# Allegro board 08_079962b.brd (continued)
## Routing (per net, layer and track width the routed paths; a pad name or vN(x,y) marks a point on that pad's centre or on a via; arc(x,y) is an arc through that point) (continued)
VIN: length 127.4
  TOP w0.254: v2(93.28,105.81) v2(92.94,105.81) v2(92.58,105.81) v2(92.23,105.81) ; R51.1 v1(89.15,83.69) ; v2(93.22,40.5) v2(92.91,40.5) v2(92.58,40.5) ; U2.11 96.16,89.67 C49.1 ; v2(92.58,106.81) v2(92.94,106.81) ; R10.1 v1(89.15,16.38) ; v2(93.22,39.5) v2(92.91,39.5) v2(92.58,39.5) v2(92.23,39.5) ; C16.1 96.16,22.36 U1.11 ; v2(92.58,107.81) v2(92.94,107.81) v2(93.28,107.81)
  TOP w0.381: JP2.3 v1(13.97,17.78)
  L2_GND w0.254: v2(91.88,107.81) v2(92.23,107.81) v2(92.58,107.81) v2(92.94,107.81) v2(93.28,107.81) ; v2(91.88,39.5) v2(92.23,39.5) v2(92.58,39.5) v2(92.91,39.5) v2(93.22,39.5) ; v2(93.22,40.5) v2(92.91,40.5) v2(92.58,40.5) v2(92.23,40.5) v2(91.88,40.5) ; v2(93.28,106.81) v2(92.94,106.81) v2(92.58,106.81) v2(92.23,106.81) v2(91.88,106.81) ; v2(91.88,38.5) v2(92.23,38.5) v2(92.58,38.5) v2(92.91,38.5) v2(93.22,38.5) ; v2(93.28,105.81) v2(92.94,105.81) v2(92.58,105.81) v2(92.23,105.81) v2(91.88,105.81)
  L4_SIG w0.381: v2(96.65,89.66) 94.74,89.66 91.69,86.61 91.69,85.72 89.66,83.69 v1(89.15,83.69) 84.46,83.69 v1(69.22,98.93) ; v1(69.22,31.62) 84.46,16.38 v1(89.15,16.38) 89.41,16.38 91.57,18.54 91.57,19.18 94.74,22.35 v2(96.71,22.35) ; v1(25.27,34.8) 13.97,23.5 v1(13.97,17.78)
  L4_SIG w0.508: v2(97.09,22.35) v2(96.71,22.35) ; v2(97.03,89.66) v2(96.65,89.66)
  L5_GND w0.254: v2(93.28,106.81) v2(92.94,106.81) v2(92.58,106.81) v2(92.23,106.81) v2(91.88,106.81) ; v2(91.88,107.81) v2(92.23,107.81) v2(92.58,107.81) v2(92.94,107.81) v2(93.28,107.81) ; v2(91.88,105.81) v2(92.23,105.81) v2(92.58,105.81) v2(92.94,105.81) v2(93.28,105.81) ; v2(93.22,40.5) v2(92.91,40.5) v2(92.58,40.5) v2(92.23,40.5) v2(91.88,40.5) ; v2(93.22,39.5) v2(92.91,39.5) v2(92.58,39.5) v2(92.23,39.5) v2(91.88,39.5) ; v2(93.22,38.5) v2(92.91,38.5) v2(92.58,38.5) v2(92.23,38.5) v2(91.88,38.5)
  vias: v1(43.81,111.25) v1(43.81,109.35) v1(43.81,107.44) v1(43.81,102.74) v1(43.81,100.84) v1(43.81,98.93) v1(43.81,43.94) v1(43.81,42.04) v1(43.81,40.13) v1(43.81,35.43) v1(43.81,33.53) v1(43.81,31.62) v1(46.35,111.25) v1(46.35,109.35) v1(46.35,107.44) v1(46.35,102.74) v1(46.35,100.84) v1(46.35,98.93) v1(46.35,43.94) v1(46.35,42.04) v1(46.35,40.13) v1(46.35,35.43) v1(46.35,33.53) v1(46.35,31.62) v1(55.24,111.25) v1(55.24,109.35) v1(55.24,107.44) v1(55.24,102.74) v1(55.24,100.84) v1(55.24,98.93) v1(55.24,43.94) v1(55.24,42.04) v1(55.24,40.13) v1(55.24,35.43) v1(55.24,33.53) v1(55.24,31.62) v1(57.79,111.25) v1(57.79,109.35) v1(57.79,107.44) v1(57.79,102.74) v1(57.79,100.84) v1(57.79,98.93) v1(57.79,43.94) v1(57.79,42.04) v1(57.79,40.13) v1(57.79,35.43) v1(57.79,33.53) v1(57.79,31.62) v1(66.67,111.25) v1(66.67,109.35) v1(66.67,107.44) v1(66.67,102.74) v1(66.67,100.84) v1(66.67,98.93) v1(66.67,43.94) v1(66.67,42.04) v1(66.67,40.13) v1(66.67,35.43) v1(66.67,33.53) v1(66.67,31.62) v1(69.22,111.25) v1(69.22,109.35) v1(69.22,107.44) v1(69.22,102.74) v1(69.22,100.84) v1(69.22,43.94) v1(69.22,42.04) v1(69.22,40.13) v1(69.22,35.43) v1(69.22,33.53) v1(89.15,39.5) v1(89.41,106.81) v1(90.04,110.11) v1(90.04,103.5) v1(90.17,108.71) v1(90.17,104.9) v1(90.17,42.8) v1(90.17,41.4) v1(90.17,37.59) v1(90.17,36.2)
CLKOUT1: length 81.5
  TOP w0.254: U1.30 v2(106.67,23.36)
  L3_SIG w0.254: JP1.2 136.94,82.64 136.27,83.31 129.41,83.31 128.02,81.91 128.02,79.63 107.82,59.44 107.82,46.74 104.39,43.31 104.39,26.16 105.66,24.89 105.66,24.37 v2(106.67,23.36)
EN1: length 130.4
  TOP w0.254: Q1.1 23.19,13.16 v1(23.11,13.08)
  TOP w0.381: R88.1 v1(23.11,126.87)
  L4_SIG w0.254: v1(23.11,126.87) 23.11,121.54 27.69,116.97 27.69,27.69 23.11,23.11 v1(23.11,13.08) 16.32,6.28 16.32,6.16 TP36.1
EN/UVLO_1: length 72.8
  TOP w0.254: R10.2 91.36,16.84 v2(91.31,16.89) ; Q2.3 v1(31.24,14.73)
  L4_SIG w0.254: TP7.1 30.48,13.97 v1(31.24,14.73) 31.62,15.11 90.55,15.11 91.31,15.88 v2(91.31,16.89)
EN/UVLO_2: length 100.3
  TOP w0.254: R51.2 v2(91.36,83.36) ; Q4.3 v1(28.7,130.68)
  L4_SIG w0.254: v2(91.36,83.36) 91.36,82.55 91.11,82.3 82.17,82.3 68.33,96.14 66.67,96.14 57.4,105.41 43.31,105.41 37.85,110.87 37.85,117.73 28.7,126.87 v1(28.7,130.68) 27.94,131.44 TP28.1
ICTRL_2: length 179.6
  TOP w0.254: R1.2 v1(105.41,14.1) ; R43.2 R44.1 107.7,85.22 106.74,86.17 U2.21
  L3_SIG w0.254: v2(107.12,83.76) 105.54,82.17 105.54,46.35 103.12,43.94 103.12,25.78 104.46,24.45 104.46,19.24 105.41,18.29 v1(105.41,14.1)
  L4_SIG w0.254: v2(107.12,83.76) 107.31,83.95 110.43,83.95 111.82,82.55 113.35,82.55 116.33,79.57 124.27,79.57 131.25,86.55 143.19,86.55 151.32,94.68 151.32,123.38 163.19,135.25 TP30.1
IGND: length 118.8
  TOP w0.254: R23.1 v2(96.27,15.18) 96.79,15.18 97.92,16.31 97.92,17.2 99.08,18.36 U1.19 ; U2.19 99.08,85.67 97.92,84.51 97.92,83.62 96.79,82.49 v2(96.27,82.49) R64.1
  L3_SIG w0.381: v2(96.27,82.49) 96.52,82.23 96.52,80.9 81.15,65.53 81.15,21.27 78.74,18.86 TP15.1
  L4_SIG w0.381: TP15.1 82.42,8.76 87.67,8.76 92.63,13.72 93.77,13.72 95.23,15.18 v2(96.27,15.18)
INJ1.1: length 83.4
  TOP w0.254: v2(112.65,16.38) R40.2 113.47,16.38 114.62,17.53 R39.1 ; TP20.1 v2(123.76,19.69)
  TOP w0.381: v2(129.67,82.11) 129.21,82.56 R93.1
  L3_SIG w0.254: v2(129.67,82.11) 129.67,77.34 121.67,69.34 121.67,21.78 v2(123.76,19.69)
  L4_SIG w0.254: v2(123.76,19.69) 121.6,17.53 113.79,17.53 v2(112.65,16.38)
INTVCC1: length 65.9
  TOP w0.254: v2(112.08,25.15) R2.1 ; R13.2 114.86,21.89 v1(114.87,21.91) 114.86,21.92 R14.2 ; C4.1 96.27,19.38 98.25,21.36 U1.13 ; v2(112.14,20.96) R6.1 ; R3.1 v2(106.55,14.1) ; D15.C v2(96.71,17.7)
  TOP w0.381: v2(95.88,14.22) TP8.1
  L3_SIG w0.254: v2(112.14,20.96) 113.92,20.96 v1(114.87,21.91) ; v2(112.14,20.96) 112.14,22.1 112.65,22.61 112.65,23.75 112.08,24.32 v2(112.08,25.15) 113.28,25.15 114.94,26.8 v2(114.94,29.08) ; v2(112.14,20.96) 111.38,20.96 109.85,19.43 109.85,17.91 106.55,14.61 v2(106.55,14.1) 106.55,13.59 105.79,12.83 97.28,12.83 v2(95.88,14.22) 95.63,14.48 95.63,16.62 v2(96.71,17.7) 96.71,21.02 90.68,27.05 v2(90.68,29.59)
  BOTTOM w0.381: D2.A 114.05,29.97 v2(114.94,29.08) ; v2(90.68,29.59) 91.06,29.97 D1.A
INTVCC2: length 67.1
  TOP w0.254: v2(112.08,92.39) 111.62,92.39 R45.1 ; R43.1 v2(106.55,81.6) ; R54.2 114.86,89.2 v1(114.87,89.22) 114.86,89.23 R55.2 ; U2.13 98.25,88.67 96.27,86.69 C37.1 ; D16.C v2(96.71,85.01) ; v2(112.14,88.26) R47.1
  TOP w0.381: TP29.1 v2(95.88,81.27)
  L3_SIG w0.254: v2(95.88,81.27) 95.5,81.65 95.5,83.81 v2(96.71,85.01) ; v2(96.71,85.01) 97.33,85.01 97.79,85.47 109.22,85.47 109.35,85.34 ; v2(96.71,85.01) 96.71,87.25 90.68,93.28 v2(90.68,97.03) ; 109.35,85.34 109.35,83.31 108.59,82.55 107.51,82.55 v2(106.55,81.6) ; 109.35,85.34 109.35,85.98 111.63,88.26 v2(112.14,88.26) 113.92,88.26 v1(114.87,89.22) 113.66,90.42 113.66,92.46 ; 113.66,92.46 113.6,92.39 v2(112.08,92.39) ; 113.66,92.46 113.66,92.96 114.94,94.23 v2(114.94,97.28)
  BOTTOM w0.381: v2(90.68,97.03) 90.93,97.28 D7.A ; v2(114.94,97.28) D8.A
ISHARE: length 117.3
  TOP w0.254: U2.20 105.77,85.28 105.41,84.92 v2(105.41,84.33) C39.1 ; C6.1 v2(104.27,17.02) 104.27,17.53 105.1,18.36 U1.20
  L3_SIG w0.381: TP11.1 91.44,9.59 86.87,14.16 86.87,17.53 82.42,21.97 82.42,64.77 101.98,84.33 v2(105.41,84.33)
  L4_SIG w0.381: TP11.1 103.38,17.02 v2(104.27,17.02)
OUT: length 131.2
  TOP w0.254: TP19.1 v2(123.76,15.88) ; 141.42,39.75 140.33,39.75 140.08,39.5 140.08,31.93 R37.1 ; 141.42,39.75 R36.2 ; 141.42,39.75 R35.2 ; R78.1 140.08,99.24 140.08,106.81 140.33,107.06 141.42,107.06 ; R40.1 v2(115.44,16.38)
  TOP w0.381: TP40.1 v2(124.4,81.28) ; R81.1 v2(115.38,83.69) ; R76.2 R77.2
  L4_SIG w0.381: v1(149.86,34.8) 148.59,33.53 148.59,26.29 138.18,15.88 v2(123.76,15.88) 115.95,15.88 v2(115.44,16.38) ; v2(115.38,83.69) 116.21,83.69 118.62,81.28 v2(124.4,81.28) 131.32,88.2 142.18,88.2 148.65,94.68 148.65,100.77 v1(147.32,102.11)
  vias: v1(144.14,114.3) v1(144.14,113.03) v1(144.14,111.76) v1(144.14,110.49) v1(144.14,109.22) v1(144.14,107.95) v1(144.14,106.68) v1(144.14,105.41) v1(144.14,104.14) v1(144.14,102.87) v1(144.14,101.6) v1(144.14,100.33) v1(144.14,46.99) v1(144.14,45.72) v1(144.14,44.45) v1(144.14,43.18) v1(144.14,41.91) v1(144.14,40.64) v1(144.14,39.37) v1(144.14,38.1) v1(144.14,36.83) v1(144.14,35.56) v1(144.14,34.29) v1(144.14,33.02) v1(147.32,113.16) v1(147.32,111.63) v1(147.32,109.98) v1(147.32,105.28) v1(147.32,103.76) v1(147.32,45.85) v1(147.32,44.32) v1(147.32,42.67) v1(147.32,37.97) v1(147.32,36.45) v1(147.32,34.8) v1(149.86,113.16) v1(149.86,111.63) v1(149.86,109.98) v1(149.86,105.28) v1(149.86,103.76) v1(149.86,102.11) v1(149.86,45.85) v1(149.86,44.32) v1(149.86,42.67) v1(149.86,37.97) v1(149.86,36.45)
PGOOD1: length 67.7
  TOP w0.254: U1.25 v2(109.35,20.86) 109.84,20.86 R6.2
  L4_SIG w0.254: v2(109.35,20.86) 108.84,20.35 108.84,17.91 111.51,15.24 112.52,15.24 117.35,10.41 158.5,10.41 TP10.1
PGOOD2: length 88.9
  TOP w0.254: U2.25 v2(109.35,88.17) 109.84,88.17 R47.2
  L4_SIG w0.254: v2(109.35,88.17) 110.52,88.17 111,87.69 114.24,87.69 114.81,88.26 119.63,88.26 120.9,89.53 138.68,89.53 145.35,96.2 145.35,130.11 150.5,135.25 TP31.1
UNNAMED_1_ADLT8292_I154_BG1N: length 3.4
  TOP w0.254: U1.2 98.79,26.86
  TOP w0.381: 98.79,26.86 98.55,27.1 R18.1
UNNAMED_1_ADLT8292_I154_BG1P: length 1.8
  TOP w0.254: 99.97,27.79 99.94,27.82 ; U1.1 99.97,27.5
  TOP w0.381: R17.1 99.69,28.07 99.94,27.82 ; 99.97,27.5 99.97,27.79
UNNAMED_1_ADLT8292_I154_BG2N: length 3.5
  TOP w0.254: 107,27.11 106.74,26.86 U1.37
  TOP w0.381: R30.1 107.19,27.3 107,27.11
UNNAMED_1_ADLT8292_I154_BG2P: length 1.9
  TOP w0.254: U1.38 105.77,27.5
  TOP w0.381: R29.1 106.04,28.07 105.77,27.79 105.77,27.5
UNNAMED_1_ADLT8292_I154_BST1: length 4.7
  TOP w0.254: U1.4 98.85,25.86 97.66,27.05 97.66,27.89 C22.1
UNNAMED_1_ADLT8292_I154_BST2: length 4.5
  TOP w0.254: C28.1 108.19,28.13 108.19,27.42 106.63,25.86 U1.35
UNNAMED_1_ADLT8292_I154_EN: length 9.3
  TOP w0.254: U1.12 97.55,21.86 96.27,20.57 91.74,20.57 C9.2
UNNAMED_1_ADLT8292_I154_ICTRL: length 55.8
  TOP w0.254: U1.21 106.74,18.86 107.7,17.91 R4.1 107.14,16.43 v2(107.12,16.45) 107.11,16.43 R3.2 R1.1
  L4_SIG w0.254: TP9.1 147.83,7.75 113.03,7.75 108.71,12.07 108.71,14.86 v2(107.12,16.45)
UNNAMED_1_ADLT8292_I154_ISN: length 52.4
  TOP w0.254: v2(98.55,19.05) 98.86,19.36 U1.17 ; R38.1 v2(138.43,27.05)
  TOP w0.381: R38.1 R38.2
  TOP w0.762: TP18.1 138.43,26.47 R38.1 ; TP17.1 141.6,26.09 R38.2
  L4_SIG w0.254: v2(138.43,27.05) 137.92,27.56 132.08,27.56 129.67,25.15 115.44,25.15 112.27,21.97 108.71,21.97 105.66,18.92 98.68,18.92 v2(98.55,19.05)
UNNAMED_1_ADLT8292_I154_LSN: length 7.4
  TOP w0.254: 94.02,23.36 C18.2 92.81,23.32 R20.1 ; 94.02,23.36 94.03,23.37 ; 94.02,23.36 U1.9
UNNAMED_1_ADLT8292_I154_LSP: length 7.9
  TOP w0.254: U1.8 96.54,23.86 95.45,24.94 C18.1 92.81,24.94 R19.1
UNNAMED_1_ADLT8292_I154_RDT1: length 7.7
  TOP w0.254: U1.26 108.86,21.36 109.19,21.69 112.24,21.69 112.6,21.34 R13.1
UNNAMED_1_ADLT8292_I154_RDT2: length 7.7
  TOP w0.254: U1.27 108.47,21.86 108.76,22.15 112.27,22.15 112.6,22.48 R14.1
UNNAMED_1_ADLT8292_I154_RT: length 4.4
  TOP w0.254: U1.28 108.21,22.36 108.76,22.91 R8.1
UNNAMED_1_ADLT8292_I154_SS: length 4.4
  TOP w0.254: C10.1 109.3,19.81 108.75,20.36 U1.24
UNNAMED_1_ADLT8292_I154_SW1: length 79.5
  TOP w0.254: v1(94.87,39.75) 95.12,39.5 M2.5 ; v1(94.87,38.48) 94.89,38.5 M2.3 ; v1(98.68,47.88) 98.68,46.86 ; v1(94.36,38.48) 94.36,38.62 93.98,39 M1.4 ; M1.6 94.11,40 v1(94.36,39.75) ; v1(93.22,37.72) 93.1,37.84 M1.2 ; v1(94.87,41.02) 94.87,41 95.38,40.5 M2.7 ; M1.8 94.34,41 v1(94.36,41.02) ; R19.2 v1(90.42,24.77) ; v1(96.9,24.64) 97.18,24.36 U1.7
  TOP w0.508: C22.2 v1(96.9,30.99) ; R26.1 95.19,46.86 102.16,46.86 R27.1
  L3_SIG w0.254: v1(98.68,47.88) 98.55,48.01 89.66,48.01 84.33,42.67 84.33,29.21 89.15,24.38 90.04,24.38 v1(90.42,24.77)
  L3_SIG w0.508: v1(94.36,38.48) 94.36,33.53 v1(96.9,30.99) v1(96.9,24.64)
  BOTTOM w0.254: 93.17,36.25 93.22,36.3 v1(93.22,37.72)
  vias: v1(94.36,42.29) v1(94.87,42.29) v1(95.25,45.97) v1(95.25,45.47) v1(95.25,44.96) v1(95.76,45.97) v1(95.76,45.47) v1(95.76,44.96) v1(96.27,45.97) v1(96.27,45.47) v1(96.27,44.96) v1(96.77,45.97) v1(96.77,45.47) v1(96.77,44.96)
UNNAMED_1_ADLT8292_I154_SW2: length 35.4
  TOP w0.254: v1(111.86,40.53) 112.33,41 M4.8 ; M3.3 110.9,38.5 v1(111.4,39.01) ; v1(111.4,41.04) 110.86,40.5 M3.7 ; U1.32 107.21,24.36 107.31,24.26 v1(107.95,24.26) ; v1(111.86,39.51) 112.35,40 M4.6 ; M3.5 110.88,39.5 v1(111.4,40.02) ; M4.4 112.36,39 v1(111.86,38.5)
  TOP w0.508: C28.2 108.84,30.4 v1(108.84,30.99) 108.84,31.71 D5.A
  L3_SIG w0.508: v1(107.95,24.26) 108.84,25.15 v1(108.84,30.99) 108.84,32.51 111,34.67 111,38.6 v1(111.4,39.01)
  BOTTOM w0.254: v2(114,37.95) v2(114.36,37.95) 114.58,37.95 114.84,37.69 114.84,36.25 114.58,35.99 J8.5
  vias: v1(110.62,52.7) v1(110.62,52.2) v1(110.87,47.37) v1(110.87,46.86) v1(110.87,46.35) v1(111.12,52.7) v1(111.12,52.2) v1(111.38,47.36) v1(111.38,46.86) v1(111.38,46.35) v1(111.4,42.8) v1(111.63,52.7) v1(111.63,52.2) v1(111.89,47.37) v1(111.89,46.86) v1(111.89,46.35) v1(111.86,42.29) v1(112.14,52.7) v1(112.14,52.19) v1(112.4,47.37) v1(112.4,46.86) v1(112.4,46.35) v1(112.65,52.7) v1(112.65,52.2) v1(113.16,52.7) v1(113.16,52.2) v2(111.58,37.85) v2(111.58,37.49) v2(111.94,37.85) v2(111.94,37.49) v2(112.3,37.85) v2(112.3,37.49) v2(114,37.59) v2(114,37.23) v2(114,36.88) v2(114.36,37.59) v2(114.36,37.23) v2(114.36,36.88)
UNNAMED_1_ADLT8292_I154_SYNC: length 81.4
  TOP w0.254: U1.29 107.82,22.86 108.71,23.75 109.68,23.75 R7.1 109.93,24.56 v2(109.92,24.57) 109.93,24.59 R2.2
  L2_GND w0.254: v2(109.92,24.57) 124.27,24.57 125.98,22.86 TP12.1
UNNAMED_1_ADLT8292_I154_TG1N: length 4.8
  TOP w0.254: U1.6 97.82,24.86 97.67,25.02
  TOP w0.381: R16.1 96.52,26.16 97.67,25.02
UNNAMED_1_ADLT8292_I154_TG1P: length 5.1
  TOP w0.254: 98.17,25.65 98.46,25.36 U1.5
  TOP w0.305: R15.1 96.52,27.3 98.17,25.65
UNNAMED_1_ADLT8292_I154_TG2N: length 4.8
  TOP w0.254: U1.33 107.54,24.86 107.7,25.02
  TOP w0.381: 107.7,25.02 108.97,26.29 R32.1
UNNAMED_1_ADLT8292_I154_TG2P: length 5
  TOP w0.254: 107.19,25.53 107.02,25.36 U1.34
  TOP w0.381: 107.19,25.53 109.09,27.43 R31.1
UNNAMED_1_ADLT8292_I154_VC: length 15.9
  TOP w0.254: U1.22 107.02,19.36 108.71,17.66 108.71,15.75 109.22,15.24 R9.1 109.93,14.68 v2(109.92,14.67) 109.93,14.66 C12.1 ; TP13.1 114.05,9.27
  L4_SIG w0.254: v2(113.98,9.27) 109.92,13.34 v2(109.92,14.67)
UNNAMED_1_ADLT8292_I154_VOUT: length 67.5
  TOP w0.254: C19.1 v1(96.39,16.32) 96.79,16.32 97.43,16.97 97.43,19.34 98.45,20.36 U1.15 ; R34.1 139.57,31.93 139.57,39.5 139.32,39.75 138.18,39.75 ; R35.1 138.23,39.81 138.18,39.75 ; R36.1 138.23,39.7 138.18,39.75
  L2_GND w0.254: v2(114.35,39.5) v2(114,39.5) v2(113.66,39.5) v2(113.32,39.5) v2(112.97,39.5) ; v2(114.35,38.5) v2(114,38.5) v2(113.66,38.5) v2(113.32,38.5) v2(112.97,38.5) ; v2(112.97,40.5) v2(113.32,40.5) v2(113.66,40.5) v2(114,40.5) v2(114.35,40.5)
  L4_SIG w0.254: v1(116.08,36.32) 116.08,28.07 112.4,24.38 111.12,24.38 110.24,23.5 107.95,23.5 105.03,20.57 97.92,20.57 97.35,20 97.35,16.83 96.84,16.32 v1(96.39,16.32)
  L5_GND w0.254: v2(114.35,38.5) v2(114,38.5) v2(113.66,38.5) v2(113.32,38.5) v2(112.97,38.5) ; v2(114.35,40.5) v2(114,40.5) v2(113.66,40.5) v2(113.32,40.5) v2(112.97,40.5) ; v2(114.35,39.5) v2(114,39.5) v2(113.66,39.5) v2(113.32,39.5) v2(112.97,39.5)
  vias: v1(115.44,43.62) v1(115.44,42.04) v1(116.08,42.8) v1(116.08,41.4) v1(116.08,37.59) v1(116.84,39.5) v1(124.46,54.7) v1(124.46,53.18) v1(124.46,51.66) v1(128.27,54.7) v1(128.27,53.18) v1(128.27,51.66) v1(132.08,54.7) v1(132.08,53.18) v1(132.08,51.66) v1(135.89,54.7) v1(135.89,53.18) v1(135.89,51.66) v1(135.89,46.99) v1(135.89,45.72) v1(135.89,44.45) v1(135.89,43.18) v1(135.89,41.91) v1(135.89,40.64) v1(135.89,39.37) v1(135.89,38.1) v1(135.89,36.83) v1(135.89,35.56) v1(135.89,34.29) v1(135.89,33.02)
UNNAMED_1_CAP_I52_N2: length 7.4
  TOP w0.254: C31.2 109.6,17.53 107.27,19.86 U1.23 ; C31.2 R41.2 ; C31.2 R42.1
UNNAMED_1_CAP_I61_N1: length 48.3
  TOP w0.254: U1.16 98.6,19.86 v2(98.3,19.56)
  TOP w0.762: TP16.1 136.91,28.45 v2(138.43,28.45) C30.1
  L4_SIG w0.254: v2(138.43,28.45) 138.05,28.07 131.83,28.07 129.41,25.65 115.19,25.65 112.01,22.48 108.46,22.48 105.54,19.56 v2(98.3,19.56)
UNNAMED_1_CNBNC5P_I74_CNTR: length 26.6
  TOP w0.254: R31.2 v1(112.14,27.43) 112.64,27.94 112.64,37.08 v1(113.15,37.59) 113.15,27.3 v1(112.14,26.29) R32.2
  BOTTOM w0.254: J8.1 113.15,35.17 v1(113.15,37.59)
UNNAMED_1_CNBNC5P_I82_CNTR: length 19.3
  TOP w0.254: R30.2 v1(107.19,31.37) 107.19,32.41 109.09,34.31 v1(109.09,37.59) 108.58,37.08 108.58,34.51 106.04,31.98 v1(106.04,31.37) R29.2
  L3_SIG w0.254: v2(106.68,36.2) 107.69,36.2 v1(109.09,37.59)
  BOTTOM w0.381: J7.1 v2(106.68,36.2)
UNNAMED_1_CNBNC5P_I107_CNTR: length 29.6
  TOP w0.254: v1(93.47,26.16) R16.2 ; 92.18,37.72 92.59,37.31 92.59,27.81 93.1,27.3 93.48,27.3 ; v1(93.47,27.3) R15.2 ; M1.1 92.07,37.72 v1(92.07,37.72) 92.07,27.18 93.1,26.16 93.48,26.16
  BOTTOM w0.254: v1(92.07,37.72) 92.07,35.69 92.84,34.92 J5.1
UNNAMED_1_CNBNC5P_I114_CNTR: length 21.7
  TOP w0.254: 96.29,37.72 96.65,37.36 96.65,34.7 99.7,31.64 99.7,31.24 ; 98.56,31.24 98.56,32.08 96.14,34.49 v1(96.14,37.72) 96.13,37.72 M2.1 ; R18.2 v1(98.55,31.24) ; R17.2 v1(99.69,31.24)
  L3_SIG w0.254: v1(96.14,37.72) 98.3,35.56 v2(99.44,35.56)
  BOTTOM w0.381: J6.1 v2(99.44,35.56)
UNNAMED_1_CNTP1P_I232_N1: length 10
  TOP w0.381: JP2.1 9.95,13.55 TP43.1
UNNAMED_1_DIOSCHOTTKY_I102_N: length 1.7
  TOP w0.508: R22.1 v1(111,30.86)
  BOTTOM w0.381: D2.C 111,30.48 v1(111,30.86)
UNNAMED_1_DIOSCHOTTKY_I103_N: length 1.7
  TOP w0.508: R21.1 v1(94.62,30.86)
  BOTTOM w0.381: v1(94.62,30.86) 94.62,30.48 D1.C
UNNAMED_1_IND_I264_N1: length 49.2
  TOP w0.254: v1(98.68,48.64) 98.68,49.66 ; R20.2 v1(90.42,23.5)
  TOP w0.508: R27.2 102.16,49.66 95.19,49.66 R26.2
  L3_SIG w0.254: v1(90.42,23.5) 90.04,23.88 88.9,23.88 83.82,28.96 83.82,42.93 89.41,48.51 98.55,48.51 v1(98.68,48.64)
  vias: v1(94.62,51.18) v1(94.62,50.67) v1(95.12,51.18) v1(95.12,50.67) v1(95.63,51.18) v1(95.63,50.67) v1(100.33,52.7) v1(100.33,52.2) v1(100.84,52.7) v1(100.84,52.2) v1(101.35,52.7) v1(101.35,52.2) v1(101.6,51.18) v1(101.6,50.67) v1(101.85,52.7) v1(101.85,52.2) v1(102.11,51.18) v1(102.11,50.67) v1(102.36,52.7) v1(102.36,52.2) v1(102.62,51.18) v1(102.62,50.67) v1(102.87,52.7) v1(102.87,52.2)
UNNAMED_1_RES_I248_N1: length 15.9
  TOP w0.381: Q3.1 20.65,129.11 v1(20.57,129.03) 20.78,128.83 R89.1 R88.2
  L4_SIG w0.254: v1(20.57,129.03) 20.57,130.56 15.24,135.89 TP44.1
UNNAMED_1_RES_I252_N1: length 130.7
  TOP w0.381: R86.1 19.3,129.49 v1(19.3,129.16) ; JP2.2 v1(14.86,15.24) 18.8,15.24 20.12,13.92 R84.1
  L4_SIG w0.381: v1(19.3,129.16) 19.3,122.81 26.54,115.57 26.54,29.46 17.78,20.7 17.78,18.16 v1(14.86,15.24)
UNNAMED_3_ADLT8292_I52_BG1N: length 3.4
  TOP w0.254: U2.2 98.79,94.17
  TOP w0.381: 98.79,94.17 98.55,94.41 R59.1
UNNAMED_3_ADLT8292_I52_BG1P: length 1.8
  TOP w0.254: U2.1 99.97,94.81 ; 99.97,95.1 99.94,95.13
  TOP w0.381: 99.97,94.81 99.97,95.1 ; 99.94,95.13 99.68,95.4 99.68,96.32 R58.1
UNNAMED_3_ADLT8292_I52_BG2N: length 3.5
  TOP w0.254: 107,94.42 106.74,94.17 U2.37
  TOP w0.381: 107,94.42 107.27,94.69 107.27,96.39 R71.1
UNNAMED_3_ADLT8292_I52_BG2P: length 1.9
  TOP w0.254: U2.38 105.77,94.81
  TOP w0.381: R70.1 106.04,95.38 105.77,95.1 105.77,94.81
UNNAMED_3_ADLT8292_I52_BST1: length 4.7
  TOP w0.254: C55.1 97.66,95.2 97.66,94.36 98.85,93.17 U2.4
UNNAMED_3_ADLT8292_I52_BST2: length 4.5
  TOP w0.254: U2.35 106.63,93.17 108.19,94.73 108.19,95.44 C61.1
UNNAMED_3_ADLT8292_I52_CLKOUT: length 20.3
  TOP w0.254: U2.30 v2(106.67,90.67)
  TOP w0.381: TP32.1 v2(124.4,90.81)
  L2_GND w0.254: v2(124.4,90.81) 123.51,91.69 114.94,91.69 114.55,91.31 110.36,91.31 109.47,90.42 106.92,90.42 v2(106.67,90.67)
UNNAMED_3_ADLT8292_I52_EN: length 9.3
  TOP w0.254: C42.2 91.74,87.88 96.39,87.88 97.68,89.17 U2.12
UNNAMED_3_ADLT8292_I52_FB: length 7.4
  TOP w0.254: U2.23 107.27,87.17 109.6,84.84 C64.2 ; C64.2 R82.2 ; C64.2 R83.1
UNNAMED_3_ADLT8292_I52_ISN: length 51.9
  TOP w0.254: v2(98.68,86.49) 98.86,86.67 U2.17 ; R79.1 v2(138.43,94.36)
  TOP w0.381: R79.1 R79.2
  TOP w0.762: R79.2 141.6,93.4 TP38.1 ; R79.1 138.43,93.78 TP39.1
  L4_SIG w0.254: v2(98.68,86.49) 106.3,86.49 108.97,89.15 112.4,89.15 115.95,92.71 133.86,92.71 135.89,94.74 138.05,94.74 v2(138.43,94.36)
UNNAMED_3_ADLT8292_I52_ISP: length 47.9
  TOP w0.254: U2.16 98.6,87.17 v2(98.43,87)
  TOP w0.762: C63.1 v2(138.43,95.76) 136.91,95.76 TP37.1
  L4_SIG w0.254: v2(98.43,87) 106.04,87 108.71,89.66 112.14,89.66 115.7,93.22 133.6,93.22 135.64,95.25 137.92,95.25 v2(138.43,95.76)
UNNAMED_3_ADLT8292_I52_LSN: length 7.4
  TOP w0.254: 94.02,90.67 94.03,90.68 ; 94.02,90.67 U2.9 ; 94.02,90.67 C51.2 92.81,90.63 R61.1
UNNAMED_3_ADLT8292_I52_LSP: length 7.9
  TOP w0.254: R60.1 92.81,92.25 C51.1 95.33,92.25 96.41,91.17 U2.8
UNNAMED_3_ADLT8292_I52_RDT1: length 7.7
  TOP w0.254: R54.1 112.6,88.65 112.24,89 109.32,89 108.99,88.67 U2.26
UNNAMED_3_ADLT8292_I52_RDT2: length 7.7
  TOP w0.254: R55.1 112.6,89.79 112.27,89.46 108.89,89.46 108.6,89.17 U2.27
UNNAMED_3_ADLT8292_I52_RT: length 4.4
  TOP w0.254: R49.1 108.76,90.22 108.21,89.67 U2.28
UNNAMED_3_ADLT8292_I52_SS: length 4.4
  TOP w0.254: U2.24 108.75,87.67 109.3,87.12 C43.1
UNNAMED_3_ADLT8292_I52_SW1: length 78.4
  TOP w0.254: R60.2 v1(90.42,92.07) ; v1(94.36,108.33) 94.34,108.31 M5.8 ; M6.7 95.39,107.81 v1(94.87,108.33) ; v1(94.87,105.79) 94.89,105.81 M6.3 ; M5.4 94.11,106.31 94.36,106.05 v1(94.36,105.79) ; M5.2 93.1,105.03 v1(93.09,105.03) ; 98.68,114.17 v1(98.68,115.19) ; v1(94.87,107.06) 95.12,106.81 M6.5 ; v1(96.9,91.95) 97.18,91.67 U2.7 ; v1(94.36,107.06) 94.11,107.31 M5.6
  TOP w0.508: R68.1 95.19,114.17 102.16,114.17 R67.1 ; C55.2 v1(96.9,98.3)
  L3_SIG w0.254: v1(98.68,115.19) 98.55,115.32 90.68,115.32 84.71,109.35 84.71,96.39 89.41,91.69 90.04,91.69 v1(90.42,92.07)
  L3_SIG w0.508: v1(96.9,91.95) v1(96.9,98.3) 94.36,100.84 v1(94.36,105.79)
  BOTTOM w0.254: J9.4 93.09,103.61 v1(93.09,105.03)
  vias: v1(94.36,109.6) v1(94.87,109.6) v1(95.25,113.28) v1(95.25,112.78) v1(95.25,112.27) v1(95.76,113.28) v1(95.76,112.78) v1(95.76,112.27) v1(96.27,113.28) v1(96.27,112.78) v1(96.27,112.27) v1(96.77,113.28) v1(96.77,112.78) v1(96.77,112.27)
UNNAMED_3_ADLT8292_I52_SW2: length 36
  TOP w0.254: v1(111.86,107.84) 111.83,107.81 M7.7 ; M7.3 110.9,105.81 v1(111.4,106.32) ; v1(111.86,106.82) 112.35,107.31 M8.6 ; v1(111.4,107.33) 110.88,106.81 M7.5 ; v1(111.86,105.81) 112.36,106.31 M8.4 ; U2.32 107.77,91.67 107.8,91.69 v1(108.33,91.69) ; M8.8 111.44,108.31 v1(111.4,108.35)
  TOP w0.381: D11.A 108.71,98.89 v1(108.71,98.3)
  TOP w0.508: C61.2 v1(108.71,98.3)
  L3_SIG w0.508: v1(111.4,106.32) 111,105.91 111,101.98 108.71,99.69 v1(108.71,98.3) 108.71,92.07 v1(108.33,91.69)
  BOTTOM w0.254: v2(114,105.26) v2(114.36,105.26) 114.58,105.26 114.84,105 114.84,103.56 114.58,103.3 J12.5
  vias: v1(110.62,120.01) v1(110.62,119.51) v1(110.74,114.68) v1(110.74,114.17) v1(110.74,113.66) v1(111.12,120.01) v1(111.12,119.51) v1(111.25,114.68) v1(111.25,114.17) v1(111.25,113.66) v1(111.4,110.11) v1(111.63,120.01) v1(111.63,119.51) v1(111.76,114.68) v1(111.76,114.17) v1(111.76,113.66) v1(111.86,109.6) v1(112.14,120.01) v1(112.14,119.51) v1(112.27,114.68) v1(112.27,114.17) v1(112.27,113.66) v1(112.65,120.01) v1(112.65,119.51) v1(113.16,120.01) v1(113.16,119.51) v2(111.58,105.16) v2(111.58,104.8) v2(111.94,105.16) v2(111.94,104.8) v2(112.3,105.16) v2(112.3,104.8) v2(114,104.9) v2(114,104.54) v2(114,104.19) v2(114.36,104.9) v2(114.36,104.54) v2(114.36,104.19)
UNNAMED_3_ADLT8292_I52_SYNC: length 106.3
  TOP w0.254: R45.2 109.93,91.9 v2(109.92,91.88) 109.93,91.87 R48.1 109.68,91.06 108.71,91.06 107.82,90.17 U2.29
  L2_GND w0.254: v2(109.92,91.88) 114.11,91.88 114.94,92.71 124.21,92.71 136.27,80.65 JP1.1
  L4_SIG w0.254: JP1.1 140.84,80.65 154.5,94.3 154.5,97.6 181.99,125.09 TP33.1
UNNAMED_3_ADLT8292_I52_TG1N: length 4.8
  TOP w0.254: 97.67,92.33 97.82,92.17 U2.6
  TOP w0.381: 97.67,92.33 96.52,93.47 R57.1
UNNAMED_3_ADLT8292_I52_TG1P: length 5.1
  TOP w0.254: 98.17,92.84 98.34,92.67 U2.5
  TOP w0.381: R56.1 95.81,94.49 96.52,94.49 98.17,92.84
UNNAMED_3_ADLT8292_I52_TG2N: length 4.8
  TOP w0.254: 107.82,92.39 107.6,92.17 U2.33
  TOP w0.381: R73.1 109.03,93.6 107.82,92.39
UNNAMED_3_ADLT8292_I52_TG2P: length 5
  TOP w0.254: U2.34 107.08,92.67 107.31,92.9 ; 109.87,94.68 R72.1
  TOP w0.381: 109.87,94.68 109.09,94.68 107.31,92.9
UNNAMED_3_ADLT8292_I52_VC: length 15.9
  TOP w0.254: U2.22 107.02,86.67 108.71,84.97 108.71,83.06 109.22,82.55 R50.1
  TOP w0.381: TP34.1 v2(113.98,76.58) ; C45.1 109.93,81.97 v2(109.92,81.98) 109.93,81.99 R50.1
  L4_SIG w0.254: v2(113.98,76.58) 109.92,80.65 v2(109.92,81.98)
UNNAMED_3_ADLT8292_I52_VOUT: length 67.8
  TOP w0.254: R75.1 139.57,99.24 139.57,106.81 139.32,107.06 138.23,107.06 ; 96.39,83.63 96.79,83.63 97.43,84.28 97.43,86.65 98.45,87.67 U2.15 ; v2(113.66,105.81) v2(113.31,105.81) ; v2(113.66,106.81) v2(113.31,106.81)
  TOP w0.381: R76.1 R77.1
  L2_GND w0.254: v2(114.38,107.81) v2(114.02,107.81) v2(113.66,107.81) v2(113.31,107.81) v2(112.97,107.81) ; v2(112.97,105.81) v2(113.31,105.81) v2(113.66,105.81) v2(114.02,105.81) v2(114.38,105.81) ; v2(114.38,106.81) v2(114.02,106.81) v2(113.66,106.81) v2(113.31,106.81) v2(112.97,106.81)
  L4_SIG w0.254: v1(96.33,83.63) 96.84,83.63 97.41,84.2 97.41,87.5 97.92,88.01 105.66,88.01 108.27,90.61 110.11,90.61 110.93,91.44 112.4,91.44 116.21,95.25 v1(116.21,103.5)
  L5_GND w0.254: v2(112.97,107.81) v2(113.31,107.81) v2(113.66,107.81) v2(114.02,107.81) v2(114.38,107.81) ; v2(114.38,105.81) v2(114.02,105.81) v2(113.66,105.81) v2(113.31,105.81) v2(112.97,105.81) ; v2(114.38,106.81) v2(114.02,106.81) v2(113.66,106.81) v2(113.31,106.81) v2(112.97,106.81)
  vias: v1(116.08,108.71) v1(116.08,104.9) v1(116.21,110.11) v1(116.84,106.81) v1(124.46,122.01) v1(124.46,120.49) v1(124.46,118.97) v1(128.27,122.01) v1(128.27,120.49) v1(128.27,118.97) v1(132.08,122.01) v1(132.08,120.49) v1(132.08,118.97) v1(134.62,114.3) v1(134.62,113.03) v1(134.62,111.76) v1(134.62,110.49) v1(134.62,109.22) v1(134.62,107.95) v1(134.62,106.68) v1(134.62,105.41) v1(134.62,104.14) v1(134.62,102.87) v1(134.62,101.6) v1(134.62,100.33) v1(135.89,122.01) v1(135.89,120.49) v1(135.89,118.97)
UNNAMED_3_CNBNC5P_I67_CNTR: length 21.8
  TOP w0.254: R59.2 v1(98.55,98.55) 98.55,99.39 96.13,101.81 v1(96.13,105.03) ; M6.1 v1(96.13,105.03) ; v1(96.13,105.03) 96.29,105.03 96.64,104.68 96.64,102.01 99.69,98.96 v1(99.69,98.55) R58.2
  L3_SIG w0.254: v2(99.44,102.87) 98.3,102.87 v1(96.13,105.03)
  BOTTOM w0.381: J10.1 v2(99.44,102.87)
UNNAMED_3_CNBNC5P_I68_CNTR: length 29.8
  TOP w0.254: M5.1 v1(92.07,105.03) ; v1(92.07,105.03) 92.17,105.03 92.58,104.63 92.58,95.13 93.09,94.62 v1(93.47,94.62) R56.2 ; v1(92.07,105.03) 92.07,94.49 93.09,93.47 v1(93.47,93.47) R57.2
  BOTTOM w0.254: J9.1 92.71,102.24 92.07,102.87 v1(92.07,105.03)
UNNAMED_3_CNBNC5P_I117_CNTR: length 19.3
  TOP w0.254: v1(106.04,98.68) 106.04,99.29 108.58,101.82 108.58,104.39 v1(109.09,104.9) 109.09,101.62 107.19,99.72 v1(107.19,98.68)
  TOP w0.381: R70.2 v1(106.04,98.68) ; R71.2 v1(107.19,98.68)
  L3_SIG w0.254: v1(109.09,104.9) 107.69,103.5 v2(106.68,103.5)
  BOTTOM w0.381: v2(106.68,103.5) J11.1
UNNAMED_3_CNBNC5P_I123_CNTR: length 26.6
  TOP w0.254: v1(112.14,93.6) 113.15,94.61 v1(113.15,104.9) 112.64,104.39 112.64,95.25 v1(112.14,94.74)
  TOP w0.381: R72.2 v1(112.14,94.74) ; R73.2 v1(112.14,93.6)
  BOTTOM w0.254: v1(113.15,104.9) 113.15,102.48 J12.1
UNNAMED_3_DIOSCHOTTKY_I96_N: length 1.7
  TOP w0.508: R62.1 v1(94.62,98.17)
  BOTTOM w0.381: v1(94.62,98.17) 94.62,97.79 D7.C
UNNAMED_3_DIOSCHOTTKY_I97_N: length 1.7
  TOP w0.508: R63.1 v1(111,98.17)
  BOTTOM w0.381: D8.C 111,97.79 v1(111,98.17)
UNNAMED_3_IND_I196_N1: length 48.1
  TOP w0.254: 98.68,116.97 v1(98.68,115.95) ; R61.2 v1(90.42,90.81)
  TOP w0.508: R67.2 102.16,116.97 95.19,116.97 R68.2
  L3_SIG w0.254: v1(98.68,115.95) 98.5,115.77 90.37,115.77 84.2,109.6 84.2,96.25 89.27,91.19 90.04,91.19 v1(90.42,90.81)
  vias: v1(94.49,118.75) v1(94.49,118.24) v1(95,118.75) v1(95,118.24) v1(95.5,118.75) v1(95.5,118.24) v1(100.2,120.01) v1(100.2,119.51) v1(100.71,120.01) v1(100.71,119.51) v1(101.22,120.01) v1(101.22,119.51) v1(101.73,120.01) v1(101.73,119.51) v1(101.85,118.75) v1(101.85,118.24) v1(102.24,120.01) v1(102.24,119.51) v1(102.36,118.75) v1(102.36,118.24) v1(102.74,120.01) v1(102.74,119.51) v1(102.87,118.75) v1(102.87,118.24)
UNNAMED_3_NCTESTPAD_I137_N1: length 18.9
  TOP w0.254: R80.1 114.62,84.84 113.47,83.69 R81.2
  TOP w0.381: R93.2 127,82.8 125.35,84.46 TP41.1 v2(124.4,84.46) ; R81.2 v2(112.71,83.69)
  L4_SIG w0.254: v2(112.71,83.69) 113.92,84.9 123.95,84.9 v2(124.4,84.46)

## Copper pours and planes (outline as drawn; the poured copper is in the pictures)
GND_SIGNAL on TOP: 121.16,43.18 121.16,35.81 117.98,35.81 117.67,36.13 117.67,42.74 118.11,43.18
GND_SIGNAL on TOP: 121.16,110.49 121.16,103.12 118.11,103.12 117.6,103.63 117.6,109.98 118.11,110.49
GND_SIGNAL on TOP: 1.27,143.51 189.23,143.51 189.23,1.27 1.27,1.27 ; 3 cut-outs
GND_SIGNAL on TOP: 85.09,110.49 85.09,103.12 88.14,103.12 88.65,103.63 88.65,109.98 88.14,110.49
GND_SIGNAL on TOP: 84.96,43.18 84.96,35.81 88.14,35.81 88.58,36.26 88.58,42.74 88.14,43.18
GND_SIGNAL on BOTTOM: 1.27,143.51 189.23,143.51 189.23,1.27 1.27,1.27 ; 8 cut-outs
GND_SIGNAL on BOTTOM: 88.26,110.36 88.58,110.05 88.58,103.44 88.39,103.25 85.09,103.25 85.09,110.36
GND_SIGNAL on BOTTOM: 88.39,42.93 88.58,42.74 88.58,36.26 88.39,36.07 84.96,36.07 84.96,42.93
GND_SIGNAL on BOTTOM: 117.86,36.07 117.67,36.26 117.67,42.74 117.86,42.93 121.16,42.93 121.16,36.07
GND_SIGNAL on BOTTOM: 117.86,103.38 117.67,103.57 117.67,110.05 117.86,110.24 121.16,110.24 121.16,103.38
GND_SIGNAL on L2_GND: 1.27,143.51 189.23,143.51 189.23,1.27 1.27,1.27 ; 7 cut-outs
GND_SIGNAL on L3_SIG: 1.27,143.51 189.23,143.51 189.23,1.27 1.27,1.27
GND_SIGNAL on L4_SIG, L5_GND: 1.27,1.27 1.27,143.51 189.23,143.51 189.23,1.27 ; 4 cut-outs
VIN on TOP: 3.05,114.3 90.87,114.3 90.87,111.76 91.19,111.44 91.19,108.33 91.57,107.95 93.41,107.95 93.47,107.89 93.47,107.76 93.38,107.67 91.54,107.67 91.38,107.51 91.38,107.12 91.57,106.93 93.41,106.93 93.47,106.87 93.47,106.74 93.41,106.68 91.57,106.68 91.38,106.49 91.38,106.11 91.57,105.92 93.41,105.92 93.47,105.85 93.47,105.73 93.41,105.66 91.57,105.66 91.25,105.35 91.25,100.65 85.85,95.25 43.18,95.25 42.55,94.62 42.55,48.39 43.81,47.12 90.93,47.12 90.93,44.58 91.31,44.2 91.31,40.89 91.57,40.64 93.34,40.64 93.34,40.39 91.57,40.39 91.44,40.26 91.44,39.75 91.57,39.62 93.34,39.62 93.34,39.37 91.57,39.37 91.44,39.24 91.44,38.73 91.57,38.61 93.34,38.61 93.34,38.35 91.57,38.35 91.44,38.23 91.44,33.53 85.47,27.56 24.77,27.56 24.77,60.96 10.79,74.93 3.05,74.93
VIN on TOP: 90.17,16.89 90.3,16.76 90.3,15.88 88.9,15.88 88.9,16.89
VIN on TOP: 90.17,84.2 90.3,84.07 90.3,83.19 88.9,83.19 88.9,84.2
VIN on TOP: 94.74,22.61 94.74,20.96 96.14,20.96 97.28,22.1 97.28,22.61
VIN on TOP: 94.74,89.92 94.74,88.26 96.14,88.26 97.28,89.41 97.28,89.92
VIN on TOP: 13.21,18.03 13.21,16.26 14.73,16.26 14.73,18.03
VIN on BOTTOM: 3.05,114.3 89.79,114.3 89.79,113.6 93.47,113.6 93.47,105.54 91.82,105.54 91.31,105.03 91.31,100.71 85.85,95.25 43.18,95.25 42.55,94.62 42.55,48.64 44.15,47.03 89.92,47.12 89.92,44.45 91.95,44.45 91.95,46.23 93.47,46.23 93.47,38.23 91.82,38.23 91.44,37.85 91.44,33.53 85.47,27.56 24.77,27.56 24.77,60.96 10.79,74.93 3.05,74.93
EN1 on TOP: 21.59,126.37 23.37,126.37 23.37,127.38 21.59,127.38
EN1 on TOP: 22.61,14.48 22.61,11.68 24,11.68 24,14.48
EN/UVLO_1 on TOP: 91.82,18.16 91.82,15.88 90.42,15.88 90.42,18.16 90.17,18.41 89.28,18.41 89.28,19.43 90.68,19.43 90.68,18.41 90.93,18.16
EN/UVLO_1 on TOP: 29.84,15.37 29.84,14.1 31.5,14.1 31.5,15.37
EN/UVLO_2 on TOP: 91.82,85.47 91.82,83.19 90.42,83.19 90.42,85.47 90.17,85.72 89.28,85.72 89.28,86.74 90.68,86.74 90.68,85.72 90.93,85.47
EN/UVLO_2 on TOP: 27.43,130.05 29.08,130.05 29.08,131.32 27.43,131.32
ICTRL_2 on TOP: 106.17,84.46 108.08,84.46 108.08,83.19 106.17,83.19
ICTRL_2 on TOP: 105.79,15.37 105.79,13.84 105.03,13.84 105.03,15.37
IGND on TOP: 95,82.87 95,82.11 96.52,82.11 96.52,82.87
IGND on TOP: 95,15.56 95,14.8 96.65,14.8 96.65,15.56
INJ1.1 on TOP: 123.55,19.69 125.37,19.69
INJ1.1 on TOP: 113.92,16 113.92,16.76 110.87,16.76 110.87,16
INJ1.1 on TOP: 129.86,83.31 129.86,81.91 128.91,81.91 128.52,82.3 128.52,83.31
INTVCC1 on TOP: 114.3,22.86 114.3,20.96 115.44,20.96 115.44,22.86
INTVCC1 on TOP: 95.17,20.19 95.17,17.07 96.29,17.07 96.9,17.68 96.9,20.19
INTVCC1 on TOP: 106.93,15.37 106.93,13.84 106.17,13.84 106.17,15.37
INTVCC1 on TOP: 94.99,13.53 96.78,13.53
INTVCC1 on TOP: 110.87,21.34 110.87,20.57 112.59,20.57 112.59,21.34
INTVCC1 on BOTTOM: 92.25,30.61 92.25,29.34 90.42,29.34 90.42,30.61
INTVCC1 on BOTTOM: 113.36,30.73 113.36,28.83 115.19,28.83 115.19,30.73
INTVCC2 on TOP: 95.17,87.5 95.17,84.38 96.29,84.38 96.9,84.99 96.9,87.5
INTVCC2 on TOP: 94.99,80.63 96.78,80.63
INTVCC2 on TOP: 110.87,92.84 110.87,92.07 112.01,92.07 112.33,92.39 112.33,92.84
INTVCC2 on TOP: 106.93,82.93 106.93,81.41 106.17,81.41 106.17,82.93
INTVCC2 on TOP: 112.33,87.88 110.74,87.88 110.74,88.65 112.33,88.65
INTVCC2 on TOP: 114.3,90.17 114.3,88.26 115.44,88.26 115.44,90.17
INTVCC2 on BOTTOM: 113.36,96.65 113.36,97.92 115.19,97.92 115.19,96.65
INTVCC2 on BOTTOM: 90.42,96.65 90.42,97.92 92.25,97.92 92.25,96.65
ISHARE on TOP: 104.65,17.21 104.65,15.75 103.89,15.75 103.89,17.21
OUT on TOP: 114.17,84.07 114.17,83.31 115.57,83.31 115.57,84.07
OUT on TOP: 114.17,16.76 114.17,16 115.7,16 115.7,16.76
OUT on TOP: 123.57,15.88 125.35,15.88
OUT on TOP: 140.08,99.31 140.08,98.11 141.1,98.11 141.1,99.31
OUT on TOP: 124.2,81.28 125.99,81.28
OUT on TOP: 139.95,48.39 139.95,40.13 140.59,40.13 140.59,32.51 166.37,32.51 166.37,62.87 179.07,75.56 187.96,75.56 187.96,115.57 139.95,115.57 139.95,107.44 140.59,107.44 140.59,99.82 151.13,99.82 151.77,99.19 151.76,48.39
OUT on TOP: 140.08,32 140.08,30.86 141.1,30.86 141.1,32
OUT on BOTTOM: 140.97,48.39 140.97,32.51 166.37,32.51 166.37,62.87 179.07,75.56 187.96,75.56 187.96,115.57 140.97,115.57 140.97,99.82 151.13,99.82 151.77,99.19 151.76,48.77 151.38,48.39
PGOOD1 on TOP: 109.09,21.34 109.09,20.57 110.62,20.57 110.62,21.34
UNNAMED_1_ADLT8292_I154_BST1 on TOP: 93.98,29.21 93.98,28.19 97.66,28.19 97.66,29.21
UNNAMED_1_ADLT8292_I154_BST2 on TOP: 108.08,28.19 111.63,28.19 111.63,29.34 108.08,29.34
UNNAMED_1_ADLT8292_I154_EN on TOP: 91.82,20.7 91.82,18.41 91.06,18.41 90.93,18.54 90.93,20.7
UNNAMED_1_ADLT8292_I154_ICTRL on TOP: 105.03,17.02 108.08,17.02 108.08,15.75 105.03,15.75
UNNAMED_1_ADLT8292_I154_ISN on TOP: 138.18,26.54 139.57,26.54 139.57,26.61 139.45,26.61 139.45,27.56 138.18,27.56
UNNAMED_1_ADLT8292_I154_ISN on TOP: 137.54,24.89 139.32,24.89
UNNAMED_1_ADLT8292_I154_ISN on TOP: 140.08,30.35 140.08,27.81 140.14,27.75 140.14,26.61 140.02,26.61 140.02,26.54 141.1,26.54 141.1,30.35
UNNAMED_1_ADLT8292_I154_ISN on TOP: 140.71,24.89 142.5,24.89
UNNAMED_1_ADLT8292_I154_LSN on TOP: 92.07,23.88 92.07,23.11 93.47,23.11 93.47,22.86 94.49,22.86 94.49,23.88
UNNAMED_1_ADLT8292_I154_LSP on TOP: 92.07,25.15 92.07,24.38 94.49,24.38 94.49,25.4 93.47,25.4 93.47,25.15
UNNAMED_1_ADLT8292_I154_RDT1 on TOP: 112.84,21.72 112.84,19.81 113.92,19.81 113.92,21.72
UNNAMED_1_ADLT8292_I154_RDT2 on TOP: 113.03,24 112.84,23.81 112.84,22.1 113.92,22.1 113.92,24
UNNAMED_1_ADLT8292_I154_SW1 on TOP: 91.69,24.38 90.17,24.38 90.17,25.15 91.69,25.15
UNNAMED_1_ADLT8292_I154_SW1 on TOP: 91.31,44.7 91.57,44.45 91.57,41.02 91.69,40.89 93.47,40.89 93.66,40.7 93.66,40.32 93.47,40.13 91.69,40.13 91.69,39.88 93.47,39.88 93.66,39.69 93.66,39.31 93.47,39.12 91.69,39.12 91.69,38.86 93.47,38.86 93.66,38.67 93.66,38.29 93.47,38.1 92.71,38.1 92.71,37.53 92.77,37.47 95.5,37.47 95.5,38.16 95.69,38.35 97.41,38.35 97.47,38.42 97.47,38.54 97.41,38.61 95.69,38.61 95.5,38.8 95.5,39.18 95.69,39.37 97.41,39.37 97.47,39.43 97.47,39.56 97.41,39.62 95.69,39.62 95.5,39.81 95.5,40.2 95.69,40.39 97.41,40.39 97.47,40.45 97.47,40.58 97.41,40.64 95.69,40.64 95.5,40.83 95.5,42.04 103.12,42.04 106.04,44.96 106.04,48.13 99.12,48.13 99.12,46.35 98.23,46.35 98.23,48.13 91.31,48.13
UNNAMED_1_ADLT8292_I154_SW1 on TOP: 96.52,29.72 96.52,32.13 97.28,32.13 97.28,29.72
UNNAMED_1_ADLT8292_I154_SW1 on BOTTOM: 92.58,33.15 96.14,33.15 96.14,36.7 92.58,36.7
UNNAMED_1_ADLT8292_I154_SW1 on BOTTOM: 91.95,48.01 91.95,46.48 93.85,46.48 93.85,37.47 95.38,37.47 95.38,44.07 95.63,44.32 97.03,44.32 99.16,42.19 104.7,42.19 104.7,47.37 94.49,47.37 93.85,48.01
UNNAMED_1_ADLT8292_I154_SW1 on L4_SIG: 92.58,38.23 92.58,46.48 98.68,46.48 98.68,41.91 95.5,41.91 95.5,38.23
UNNAMED_1_ADLT8292_I154_SW1 on L5_GND: 92.65,38.23 92.65,46.48 98.68,46.48 98.68,41.91 95.5,41.91 95.5,38.23
UNNAMED_1_ADLT8292_I154_SW2 on TOP: 107.7,59.31 115.06,59.31 115.06,49.15 114.81,48.9 114.81,41.15 114.55,40.89 112.71,40.89 112.52,40.7 112.52,40.32 112.71,40.13 114.49,40.13 114.55,40.07 114.55,39.94 114.49,39.88 112.71,39.88 112.52,39.69 112.52,39.31 112.71,39.12 114.49,39.12 114.55,39.05 114.55,38.93 114.49,38.86 112.71,38.86 112.52,38.67 112.52,37.34 111.52,37.34 110.51,38.35 108.84,38.35 108.78,38.42 108.78,38.54 108.84,38.61 110.55,38.61 110.74,38.8 110.74,39.18 110.55,39.37 108.84,39.37 108.78,39.43 108.78,39.56 108.84,39.62 110.55,39.62 110.74,39.81 110.74,40.2 110.55,40.39 108.84,40.39 108.78,40.45 108.78,40.58 108.84,40.64 110.55,40.64 110.81,40.89 110.81,41.85 107.7,44.96
UNNAMED_1_ADLT8292_I154_SW2 on TOP: 113.79,38.05 113.79,36.7 114.55,36.7 114.55,38.05 114.53,38.07 113.82,38.07
UNNAMED_1_ADLT8292_I154_SW2 on TOP: 108.33,29.72 108.33,32.13 109.09,32.13 109.09,29.72
UNNAMED_1_ADLT8292_I154_SW2 on BOTTOM: 110.87,36.45 110.87,32.89 114.43,32.89 114.43,36.45
UNNAMED_1_ADLT8292_I154_SW2 on BOTTOM: 115.06,55.47 115.06,45.85 113.69,45.85 112.12,44.27 112.12,38.23 111.15,38.23 111.15,44.45 109.22,44.45 109.22,55.47
UNNAMED_1_ADLT8292_I154_SW2 on L4_SIG: 107.82,44.83 107.82,55.12 114.94,55.12 114.94,38.34 113.41,38.34 113.41,37.74 114.51,37.74 114.51,36.73 112.13,36.73 110.74,38.12 110.74,41.91
UNNAMED_1_ADLT8292_I154_SW2 on L5_GND: 107.82,44.83 107.82,55.12 114.94,55.12 114.94,38.34 113.41,38.34 113.41,37.74 114.51,37.74 114.51,36.73 112.13,36.73 110.74,38.12 110.74,41.91
UNNAMED_1_ADLT8292_I154_SYNC on TOP: 109.35,25.53 109.35,23.62 110.62,23.62 110.62,25.53
UNNAMED_1_ADLT8292_I154_VC on TOP: 113.78,9.27 115.58,9.27
UNNAMED_1_ADLT8292_I154_VC on TOP: 110.62,15.62 110.62,13.72 109.35,13.72 109.35,15.62
UNNAMED_1_ADLT8292_I154_VOUT on TOP: 95,16.7 95,15.94 96.65,15.94 96.65,16.7
UNNAMED_1_ADLT8292_I154_VOUT on TOP: 138.56,32 138.56,30.86 139.57,30.86 139.57,32
UNNAMED_1_ADLT8292_I154_VOUT on TOP: 139.7,57.15 121.28,57.15 121.28,51.82 118.24,48.77 115.44,48.77 115.19,48.51 115.19,41.21 114.62,40.64 112.9,40.64 112.84,40.58 112.84,40.45 112.9,40.39 114.68,40.39 114.81,40.26 114.81,39.75 114.68,39.62 112.9,39.62 112.84,39.56 112.84,39.43 112.9,39.37 114.68,39.37 114.81,39.24 114.81,38.73 114.68,38.61 112.9,38.61 112.84,38.54 112.84,38.42 112.9,38.35 114.68,38.35 114.87,38.16 114.87,34.42 121.73,27.56 134.75,27.56 134.75,29.72 137.54,32.51 139.06,32.51 139.06,40.13 139.7,40.13
UNNAMED_1_ADLT8292_I154_VOUT on BOTTOM: 138.94,57.15 122.05,57.15 122.05,48.9 115.32,48.9 115.32,45.59 113.79,45.59 112.37,44.17 112.37,38.23 114.84,38.23 115.19,37.88 115.19,34.1 121.73,27.56 133.86,27.56 138.94,32.64
UNNAMED_1_CAP_I52_N1 on TOP: 113.92,17.14 113.92,17.91 110.87,17.91 110.87,17.14
UNNAMED_1_CAP_I52_N2 on TOP: 110.49,19.05 110.49,16 109.35,16 109.35,19.05
UNNAMED_1_CAP_I61_N1 on TOP: 138.56,30.35 138.56,28.96 138.18,28.96 138.18,27.94 139.57,27.94 139.57,30.35
UNNAMED_1_CAP_I61_N1 on TOP: 135.63,28.07 137.42,28.07
UNNAMED_1_CAP_I80_N1 on BOTTOM: 107.31,47.62 107.31,44.45 108.97,44.45 108.97,47.62
UNNAMED_1_CAP_I93_N1 on BOTTOM: 90.17,44.7 91.69,44.7 91.69,48.01 90.17,48.01
UNNAMED_1_CAP_I158_N1 on TOP: 113.92,14.86 113.92,15.62 110.87,15.62 110.87,14.86
UNNAMED_1_CNBNC5P_I74_CNTR on TOP: 112.52,27.05 111,27.05 111,27.81 112.52,27.81
UNNAMED_1_CNBNC5P_I74_CNTR on TOP: 112.52,25.91 111,25.91 111,26.67 112.52,26.67
UNNAMED_1_CNBNC5P_I82_CNTR on TOP: 106.81,30.23 106.81,31.75 107.57,31.75 107.57,30.23
UNNAMED_1_CNBNC5P_I82_CNTR on TOP: 105.66,30.23 105.66,31.75 106.43,31.75 106.43,30.23
UNNAMED_1_CNBNC5P_I107_CNTR on TOP: 94.62,26.92 93.22,26.92 93.22,27.69 94.62,27.69
UNNAMED_1_CNBNC5P_I107_CNTR on TOP: 94.62,25.78 93.22,25.78 93.22,26.54 94.62,26.54
UNNAMED_1_CNBNC5P_I114_CNTR on TOP: 98.17,30.1 98.17,31.62 98.93,31.62 98.93,30.1
UNNAMED_1_CNBNC5P_I114_CNTR on TOP: 99.31,30.1 99.31,31.62 100.08,31.62 100.08,30.1
UNNAMED_1_CNTP1P_I232_N1 on TOP: 13.21,14.22 13.21,12.7 14.73,12.7 14.73,14.22
UNNAMED_1_DIOSCHOTTKY_I102_N on TOP: 110.62,29.72 111.38,29.72 111.38,31.12 110.62,31.12
UNNAMED_1_DIOSCHOTTKY_I102_N on BOTTOM: 110.49,29.34 110.49,31.24 111.94,31.24 111.94,29.34
UNNAMED_1_DIOSCHOTTKY_I103_N on TOP: 94.23,29.72 95,29.72 95,31.12 94.23,31.12
UNNAMED_1_DIOSCHOTTKY_I103_N on BOTTOM: 93.68,31.24 95.12,31.24 95.12,29.34 93.68,29.34
UNNAMED_1_DIOZNR_I191_N on TOP: 96.14,29.72 96.14,32.13 95.38,32.13 95.38,29.72
UNNAMED_1_DIOZNR_I193_N on TOP: 109.47,29.72 109.47,32.13 110.49,32.13 110.49,31.37 110.24,31.37 110.24,29.72
UNNAMED_1_IND_I264_N1 on TOP: 91.69,23.11 90.17,23.11 90.17,23.88 91.69,23.88
UNNAMED_1_IND_I264_N1 on TOP: 91.31,59.31 91.31,48.39 98.23,48.39 98.23,50.16 99.12,50.16 99.12,48.39 106.04,48.39 106.04,59.31
UNNAMED_1_IND_I264_N1 on BOTTOM: 103.25,50.29 103.25,55.47 94.23,55.47 94.23,50.29
UNNAMED_1_IND_I264_N1 on L4_SIG: 93.73,49.91 93.73,55.12 103.76,55.12 103.76,49.91
UNNAMED_1_IND_I264_N1 on L5_GND: 93.73,55.12 93.73,49.91 103.76,49.91 103.76,55.12
UNNAMED_1_RES_I231_N1 on TOP: 20.96,16.38 20.96,14.99 28.96,14.99 28.96,16.38
UNNAMED_1_RES_I241_N1 on TOP: 18.41,132.33 18.41,130.94 26.42,130.94 26.42,132.33
UNNAMED_1_RES_I248_N1 on TOP: 20.07,130.43 20.07,126.37 21.34,126.37 21.34,130.43
UNNAMED_1_RES_I252_N1 on TOP: 20.96,14.61 20.96,13.34 22.1,13.34 22.1,14.61
UNNAMED_1_RES_I252_N1 on TOP: 18.41,130.56 18.41,128.91 19.69,128.91 19.69,130.56
UNNAMED_1_RES_I252_N1 on TOP: 13.21,15.88 13.21,14.61 15.11,14.61 15.11,15.88
UNNAMED_3_ADLT8292_I52_BST1 on TOP: 93.98,96.52 93.98,95.5 97.66,95.5 97.66,96.52
UNNAMED_3_ADLT8292_I52_BST2 on TOP: 108.08,95.5 111.63,95.5 111.63,96.65 108.08,96.65
UNNAMED_3_ADLT8292_I52_CLKOUT on TOP: 124.21,90.81 125.98,90.81
UNNAMED_3_ADLT8292_I52_EN on TOP: 91.82,88.01 91.82,85.72 91.06,85.72 90.93,85.85 90.93,88.01
UNNAMED_3_ADLT8292_I52_FB on TOP: 110.49,86.36 110.49,83.31 109.22,83.31 109.22,86.36
UNNAMED_3_ADLT8292_I52_ISN on TOP: 140.71,92.2 142.5,92.2
UNNAMED_3_ADLT8292_I52_ISN on TOP: 140.08,97.6 140.08,95.06 140.14,95 140.14,93.93 140.02,93.93 140.02,93.85 141.1,93.85 141.1,97.6
UNNAMED_3_ADLT8292_I52_ISN on TOP: 138.18,93.85 139.57,93.85 139.57,93.93 139.45,93.93 139.45,94.87 138.18,94.87
UNNAMED_3_ADLT8292_I52_ISN on TOP: 137.54,92.2 139.32,92.2
UNNAMED_3_ADLT8292_I52_ISP on TOP: 138.56,97.6 138.56,96.2 138.18,96.2 138.18,95.19 139.57,95.19 139.57,97.6
UNNAMED_3_ADLT8292_I52_ISP on TOP: 135.63,95.38 137.42,95.38
UNNAMED_3_ADLT8292_I52_LSN on TOP: 92.07,91.19 92.07,90.42 93.47,90.42 93.47,90.17 94.49,90.17 94.49,91.19
UNNAMED_3_ADLT8292_I52_LSP on TOP: 92.07,92.46 92.07,91.69 94.49,91.69 94.49,92.71 93.47,92.71 93.47,92.46
UNNAMED_3_ADLT8292_I52_RDT1 on TOP: 112.84,89.03 112.84,87.12 113.92,87.12 113.92,89.03
UNNAMED_3_ADLT8292_I52_RDT2 on TOP: 113.03,91.31 112.84,91.12 112.84,89.41 113.92,89.41 113.92,91.31
UNNAMED_3_ADLT8292_I52_SW1 on TOP: 91.69,91.69 90.17,91.69 90.17,92.46 91.69,92.46
UNNAMED_3_ADLT8292_I52_SW1 on TOP: 91.31,112.01 91.57,111.76 91.57,108.33 91.69,108.2 93.54,108.2 93.73,108.01 93.73,107.63 93.51,107.42 91.73,107.42 91.69,107.38 91.69,107.25 91.73,107.21 93.51,107.21 93.73,107 93.73,106.62 93.54,106.43 91.76,106.43 91.69,106.36 91.69,106.24 91.76,106.17 93.54,106.17 93.73,105.98 93.73,105.6 93.54,105.41 92.71,105.41 92.71,104.84 92.77,104.78 94.74,104.78 95.63,105.66 97.41,105.66 97.47,105.73 97.47,105.85 97.41,105.92 95.69,105.92 95.5,106.11 95.5,106.49 95.69,106.68 97.41,106.68 97.47,106.74 97.47,106.87 97.41,106.93 95.69,106.93 95.5,107.12 95.5,107.51 95.69,107.7 97.41,107.7 97.47,107.76 97.47,107.89 97.41,107.95 95.69,107.95 95.5,108.14 95.5,109.35 103,109.35 106.04,112.4 106.04,115.44 99.12,115.44 99.12,113.66 98.23,113.66 98.23,115.44 91.31,115.44
UNNAMED_3_ADLT8292_I52_SW1 on TOP: 96.52,96.9 96.52,99.31 97.28,99.31 97.28,96.9
UNNAMED_3_ADLT8292_I52_SW1 on BOTTOM: 92.58,100.46 96.14,100.46 96.14,104.01 92.58,104.01
UNNAMED_3_ADLT8292_I52_SW1 on BOTTOM: 91.82,115.57 91.82,113.79 93.79,113.79 93.79,105.54 95.44,105.54 95.44,111.51 95.57,111.63 96.9,111.63 99.03,109.5 104.7,109.5 104.7,114.68 94.74,114.68 93.85,115.57
UNNAMED_3_ADLT8292_I52_SW1 on L4_SIG, L5_GND: 92.58,105.54 92.58,113.66 98.43,113.66 98.43,109.22 95.5,109.22 95.5,105.54
UNNAMED_3_ADLT8292_I52_SW2 on TOP: 108.33,97.03 108.33,99.44 109.09,99.44 109.09,97.03
UNNAMED_3_ADLT8292_I52_SW2 on TOP: 113.79,105.36 113.79,104.01 114.55,104.01 114.55,105.36 114.53,105.38 113.82,105.38
UNNAMED_3_ADLT8292_I52_SW2 on TOP: 107.7,126.62 115.06,126.62 115.06,116.46 114.81,116.21 114.81,108.46 114.55,108.2 112.71,108.2 112.52,108.01 112.52,107.63 112.74,107.42 114.52,107.42 114.55,107.38 114.55,107.25 114.49,107.19 112.71,107.19 112.52,107 112.52,106.62 112.71,106.43 114.49,106.43 114.55,106.36 114.55,106.24 114.49,106.17 112.71,106.17 112.52,105.98 112.52,104.65 111.52,104.65 110.51,105.66 108.84,105.66 108.78,105.73 108.78,105.85 108.84,105.92 110.55,105.92 110.74,106.11 110.74,106.49 110.55,106.68 108.84,106.68 108.78,106.74 108.78,106.87 108.84,106.93 110.55,106.93 110.74,107.12 110.74,107.51 110.55,107.7 108.84,107.7 108.78,107.76 108.78,107.89 108.84,107.95 110.55,107.95 110.74,108.14 110.74,109.35 107.7,112.4
UNNAMED_3_ADLT8292_I52_SW2 on BOTTOM: 110.87,103.76 110.87,100.2 114.43,100.2 114.43,103.77 113.55,103.77 113.54,103.76
UNNAMED_3_ADLT8292_I52_SW2 on BOTTOM: 115.06,122.78 115.06,113.16 113.51,113.16 112.12,111.76 112.12,105.55 111.15,105.55 111.15,111.89 109.22,111.89 109.22,122.78
UNNAMED_3_ADLT8292_I52_SW2 on L4_SIG, L5_GND: 107.7,112.27 107.7,122.3 115,122.3 115,105.65 113.4,105.65 113.4,105.05 114.51,105.05 114.51,104.04 112.13,104.04 110.77,105.4 110.77,109.19
UNNAMED_3_ADLT8292_I52_SYNC on TOP: 109.22,92.84 109.22,90.93 110.49,90.93 110.49,92.84
UNNAMED_3_ADLT8292_I52_VC on TOP: 110.49,82.93 110.49,81.03 109.22,81.03 109.22,82.93
UNNAMED_3_ADLT8292_I52_VC on TOP: 113.79,76.58 115.57,76.58
UNNAMED_3_ADLT8292_I52_VOUT on TOP: 95,84.01 95,83.25 96.65,83.25 96.65,84.01
UNNAMED_3_ADLT8292_I52_VOUT on TOP: 139.7,124.46 121.28,124.46 121.28,119 118.36,116.08 115.44,116.08 115.19,115.82 115.19,108.52 114.62,107.95 112.9,107.95 112.84,107.89 112.84,107.76 112.93,107.67 114.71,107.67 114.81,107.57 114.81,107.06 114.68,106.93 112.9,106.93 112.84,106.87 112.84,106.74 112.9,106.68 114.68,106.68 114.81,106.55 114.81,106.04 114.68,105.92 112.9,105.92 112.84,105.85 112.84,105.73 112.9,105.66 114.68,105.66 114.87,105.47 114.87,101.73 121.73,94.87 134.75,94.87 134.75,97.03 137.54,99.82 139.06,99.82 139.06,107.44 139.7,107.44
UNNAMED_3_ADLT8292_I52_VOUT on TOP: 138.56,99.31 138.56,98.11 139.57,98.11 139.57,99.31
UNNAMED_3_ADLT8292_I52_VOUT on BOTTOM: 138.81,124.59 121.92,124.59 121.92,116.33 115.32,116.33 115.32,112.9 113.64,112.9 112.37,111.63 112.37,105.54 114.84,105.54 115.13,105.25 115.13,101.47 121.6,95 133.73,95 138.81,100.08
UNNAMED_3_CAP_I32_N1 on TOP: 113.92,82.17 113.92,82.93 110.87,82.93 110.87,82.17
UNNAMED_3_CAP_I110_N1 on BOTTOM: 108.84,114.94 108.84,111.89 107.19,111.89 107.19,114.94
UNNAMED_3_CAP_I128_N1 on TOP: 113.92,84.46 113.92,85.22 110.87,85.22 110.87,84.46
UNNAMED_3_CNBNC5P_I67_CNTR on TOP: 99.31,97.41 99.31,98.81 100.08,98.81 100.08,97.41
UNNAMED_3_CNBNC5P_I67_CNTR on TOP: 98.17,97.41 98.17,98.81 98.93,98.81 98.93,97.41
UNNAMED_3_CNBNC5P_I68_CNTR on TOP: 94.62,93.09 93.22,93.09 93.22,93.85 94.62,93.85
UNNAMED_3_CNBNC5P_I68_CNTR on TOP: 94.62,94.23 93.22,94.23 93.22,95 94.62,95
UNNAMED_3_CNBNC5P_I68_CNTR on TOP: 92.41,105.41 92.44,105.4 92.46,105.36 92.46,104.83 92.44,104.79 92.41,104.78 91.74,104.78 91.71,104.79 91.69,104.83 91.69,105.33 91.7,105.34 91.71,105.36 91.74,105.4 91.76,105.41 91.78,105.41
UNNAMED_3_CNBNC5P_I117_CNTR on TOP: 105.66,97.54 105.66,98.93 106.43,98.93 106.43,97.54
UNNAMED_3_CNBNC5P_I117_CNTR on TOP: 106.81,97.54 106.81,98.93 107.57,98.93 107.57,97.54
UNNAMED_3_CNBNC5P_I123_CNTR on TOP: 112.4,93.22 111,93.22 111,93.98 112.4,93.98
UNNAMED_3_CNBNC5P_I123_CNTR on TOP: 112.4,94.36 111,94.36 111,95.12 112.4,95.12
UNNAMED_3_DIOSCHOTTKY_I96_N on TOP: 94.23,96.9 95,96.9 95,98.43 94.23,98.43
UNNAMED_3_DIOSCHOTTKY_I96_N on BOTTOM: 93.68,96.65 93.68,98.43 95.12,98.43 95.12,96.65
UNNAMED_3_DIOSCHOTTKY_I97_N on TOP: 110.62,97.03 111.38,97.03 111.38,98.43 110.62,98.43
UNNAMED_3_DIOSCHOTTKY_I97_N on BOTTOM: 111.94,96.65 111.94,98.43 110.49,98.43 110.49,96.65
UNNAMED_3_DIOZNR_I108_N on TOP: 96.14,96.9 96.14,99.31 95.38,99.31 95.38,96.9
UNNAMED_3_DIOZNR_I113_N on TOP: 109.47,97.03 109.47,99.44 110.49,99.44 110.49,98.68 110.24,98.68 110.24,97.03
UNNAMED_3_IND_I196_N1 on TOP: 91.31,126.49 91.31,115.7 98.23,115.7 98.23,117.47 99.12,117.47 99.12,115.7 106.04,115.7 106.04,126.49
UNNAMED_3_IND_I196_N1 on TOP: 91.69,90.42 90.17,90.42 90.17,91.19 91.69,91.19
UNNAMED_3_IND_I196_N1 on BOTTOM: 103.25,117.86 103.25,122.78 94.11,122.78 94.11,117.86
UNNAMED_3_IND_I196_N1 on L4_SIG, L5_GND: 93.73,122.3 93.73,117.35 103.76,117.35 103.76,122.3
UNNAMED_3_NCTESTPAD_I137_N1 on TOP: 124.21,84.46 125.98,84.46
UNNAMED_3_NCTESTPAD_I137_N1 on TOP: 128.27,83.31 128.27,82.3 127,82.3 127,83.31
UNNAMED_3_NCTESTPAD_I137_N1 on TOP: 113.92,83.31 113.92,84.07 110.87,84.07 110.87,83.31

Small or netless copper shapes (teardrops, artwork), in the pictures only: 33 on TOP, 1 on BOTTOM, 2 on L2_GND, 15 on L3_SIG, 20 on L4_SIG

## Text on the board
Ref Des/Assembly Bottom: C | A
